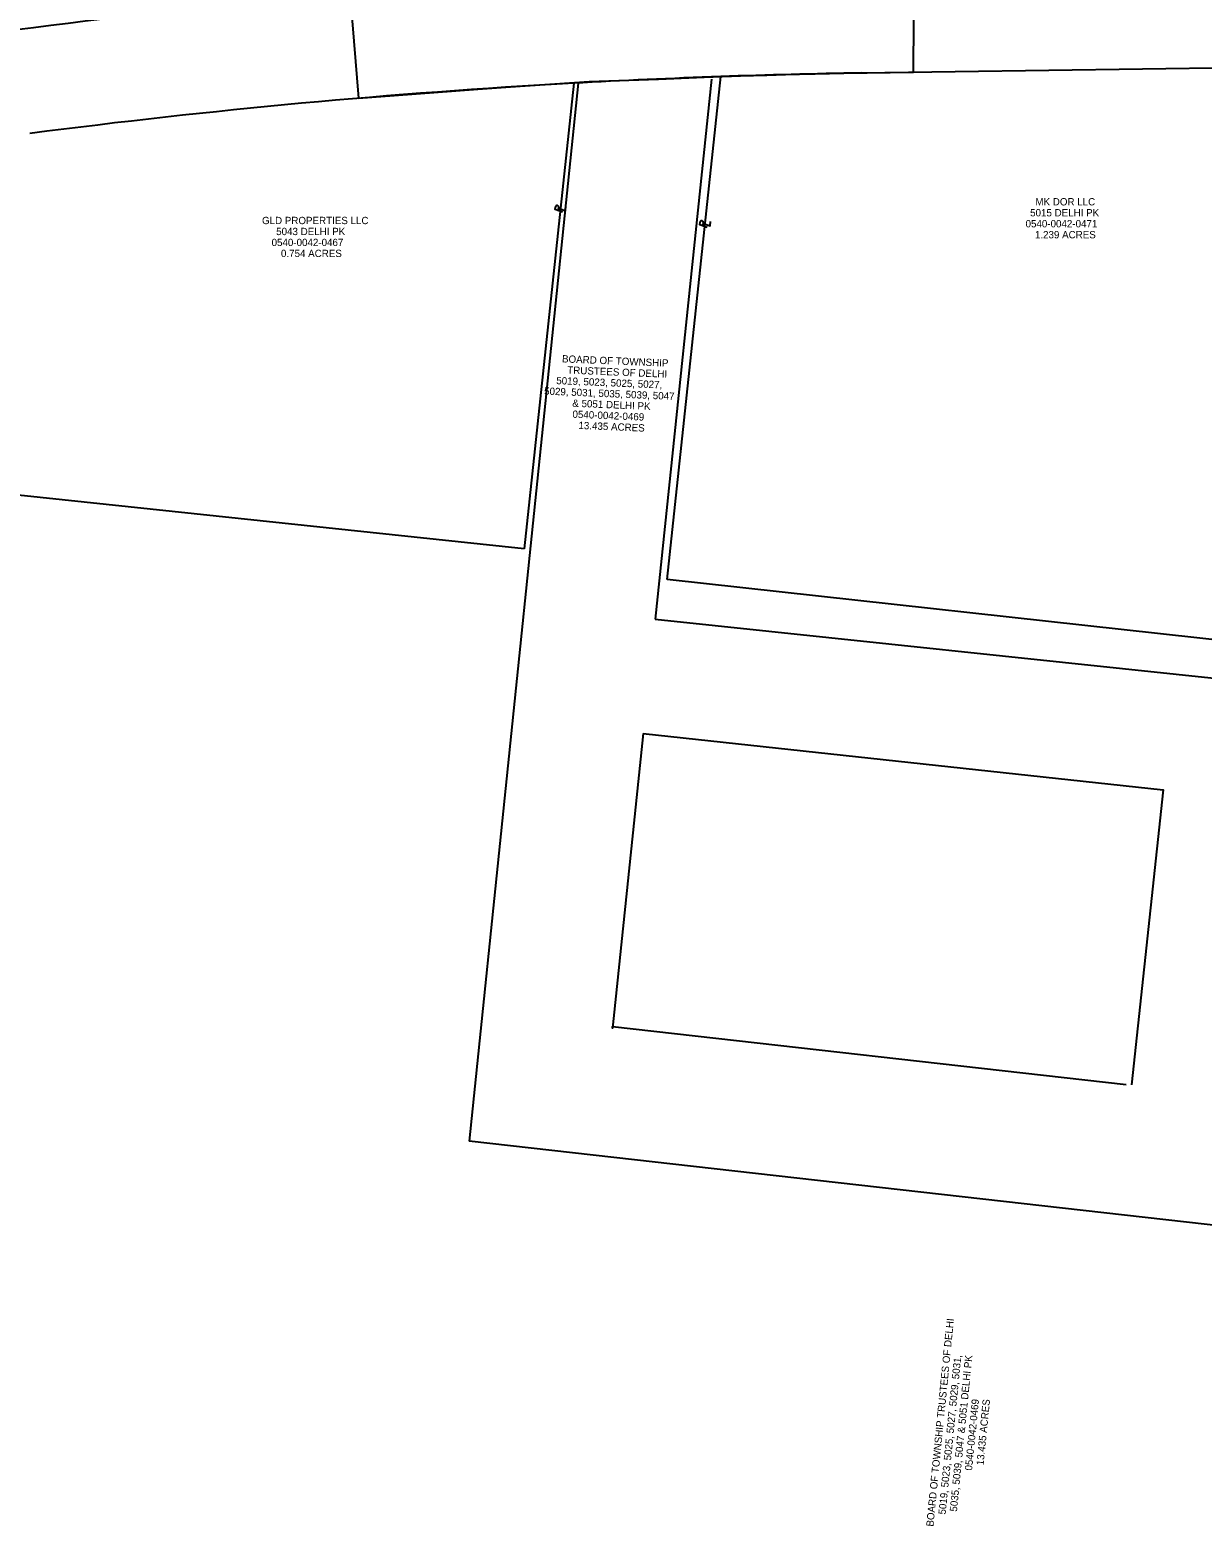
# Model space of a CAD drawing. Extents: x 1369159 to 1370720, y 404461 to 406422.
# Drawn here: x 1369471 to 1369920, y 405311 to 405884 of the extents above; entities that cross this region are included whole.
import ezdxf

# ---------------------------------------------------------------- set-up
doc = ezdxf.new("R2010")
doc.units = 0
for name, color, linetype in [('Default', 7, 'Continuous'), ('DR_P_Storm_Sewer', 7, 'Continuous'), ('DR_X_Cells', 7, 'Continuous'), ('GK_Drainage_Nodes', 7, 'Continuous'), ('PF_X_Ground_Line', 7, 'Continuous'), ('XS_X_Pavt', 7, 'Continuous'), ('XS_X_Subgrade', 7, 'Continuous')]:
    doc.layers.add(name, color=color, linetype=linetype)

msp = doc.modelspace()

# ---------------------------------------------------------------- linework, layer by layer
at = {"layer": 'Default'}
for p, q in [((1369710.16, 405658.01), (1369710.16, 405658.01)), ((1369705.59, 405614.29), (1369705.59, 405614.29))]:
    msp.add_line(p, q, dxfattribs=at)
at = {"layer": 'DR_P_Storm_Sewer'}
for p, q in [((1369679.01, 405863.29), (1369660.06, 405685)), ((1369714.82, 405673.24), (1369735.28, 405865.83)), ((1369673.19, 405814.46), (1369673.33, 405815.75)), ((1369673.9, 405815.2), (1369673.9, 405815.2)), ((1369728.57, 405808.62), (1369728.71, 405809.91)), ((1369729.28, 405809.36), (1369729.28, 405809.36)), ((1369660.06, 405685), (1369455.76, 405706.68)), ((1369970.15, 405645.1), (1369714.82, 405673.24))]:
    msp.add_line(p, q, dxfattribs=at)
for points in [[(1369674.73, 405813.88), (1369671.86, 405814.97), (1369671.97, 405815.99)], [(1369672.97, 405815.56), (1369675.83, 405814.47), (1369676.01, 405816.2)], [(1369730.11, 405808.04), (1369727.25, 405809.13), (1369727.36, 405810.15)], [(1369728.35, 405809.72), (1369731.21, 405808.62), (1369731.39, 405810.36)]]:
    msp.add_lwpolyline(points, dxfattribs=at)
for centre in [(1369672.64, 405815.82), (1369728.02, 405809.98)]:
    msp.add_arc(centre, 0.69, 354.4812, 165.3383, dxfattribs=at)
at = {"layer": 'DR_X_Cells'}
msp.add_lwpolyline([(1369642.22, 405861.02), (1369654.84, 405861.85), (1369684.92, 405863.95), (1369711.42, 405864.9), (1369728.97, 405865.6), (1369742.82, 405866.07), (1369752.88, 405866.4), (1369760.07, 405866.6), (1369765.46, 405866.74), (1369771.5, 405866.85), (1369782.46, 405867.11), (1369809.08, 405867.51), (1369809.6, 405947.53), (1369754.89, 405946.35), (1369739.98, 405945.96), (1369704.61, 405944.67), (1369686.9, 405943.7), (1369644.28, 405941.34), (1369590.13, 405937.27), (1369596.55, 405857.52), (1369610.3, 405858.65)], close=True, dxfattribs=at)
at = {"layer": 'PF_X_Ground_Line'}
for p, q in [((1369680.66, 405863.27), (1369638.99, 405458.25)), ((1369731.76, 405864.8), (1369710.16, 405658.01)), ((1369710.16, 405658.01), (1369968.29, 405630.88))]:
    msp.add_line(p, q, dxfattribs=at)
for points in [[(1369705.59, 405614.29), (1369693.81, 405501.45), (1369693.88, 405502.04), (1369890.6, 405479.89)], [(1369705.59, 405614.29), (1369904.77, 405592.76), (1369892.55, 405479.75)], [(1369946.39, 405423.64), (1369921.62, 405426.31), (1369638.99, 405458.25)]]:
    msp.add_lwpolyline(points, dxfattribs=at)
at = {"layer": 'XS_X_Pavt'}
msp.add_arc((1369834.84, 403043.1), 2864.49, 93.16294, 97.40586, dxfattribs=at)
at = {"layer": 'XS_X_Subgrade'}
msp.add_line((1369789.17, 405867.23), (1369977.07, 405869.94), dxfattribs=at)
for centre, radius, start, end in [((1369834.86, 403042.81), 2824.79, 93.16292, 97.40584), ((1369830.65, 403126.66), 2740.83, 91.9941, 93.17167), ((1369832.95, 403134.22), 2733.35, 90.91781, 92.04778)]:
    msp.add_arc(centre, radius, start, end, dxfattribs=at)

# ---------------------------------------------------------------- texts
at = {"layer": 'GK_Drainage_Nodes'}
for s, p in [('MK DOR LLC', (1369855.79, 405816.5)), ('GLD PROPERTIES LLC', (1369559.63, 405809.33)), ('0540-0042-0471', (1369852.02, 405808.1)), ('5015 DELHI PK', (1369853.77, 405812.3)), ('5043 DELHI PK', (1369565.06, 405805.13)), ('1.239 ACRES', (1369855.6, 405803.9)), ('0540-0042-0467', (1369563.3, 405800.93)), ('0.754 ACRES', (1369566.89, 405796.73))]:
    msp.add_text(s, height=2.8, dxfattribs=at).set_placement(p)
for s, rotation, p in [('BOARD OF TOWNSHIP ', 357.6387, (1369674.47, 405756.4)), ('TRUSTEES OF DELHI', 357.6387, (1369676.47, 405752.11)), ('5019, 5023, 5025, 5027,', 357.6387, (1369672.27, 405748.08)), (' 5029, 5031, 5035, 5039, 5047 ', 357.6387, (1369666.57, 405744.11)), ('& 5051 DELHI PK', 357.6387, (1369678.41, 405739.42)), ('0540-0042-0469', 357.6387, (1369678.47, 405735.21)), ('13.435 ACRES', 357.6387, (1369680.75, 405730.92)), ('BOARD OF TOWNSHIP TRUSTEES OF DELHI', 84.3389, (1369816.72, 405310.51)), ('5019, 5023, 5025, 5027, 5029, 5031, ', 84.3389, (1369821.4, 405315.13)), ('5035, 5039, 5047 & 5051 DELHI PK', 84.3389, (1369825.73, 405316.24)), ('0540-0042-0469', 84.3389, (1369831.51, 405331.96)), ('13.435 ACRES', 84.3389, (1369835.93, 405333.99))]:
    msp.add_text(s, height=2.8, rotation=rotation, dxfattribs=at).set_placement(p)

doc.saveas('drawing.dxf')
